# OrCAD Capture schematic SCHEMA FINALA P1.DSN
size A
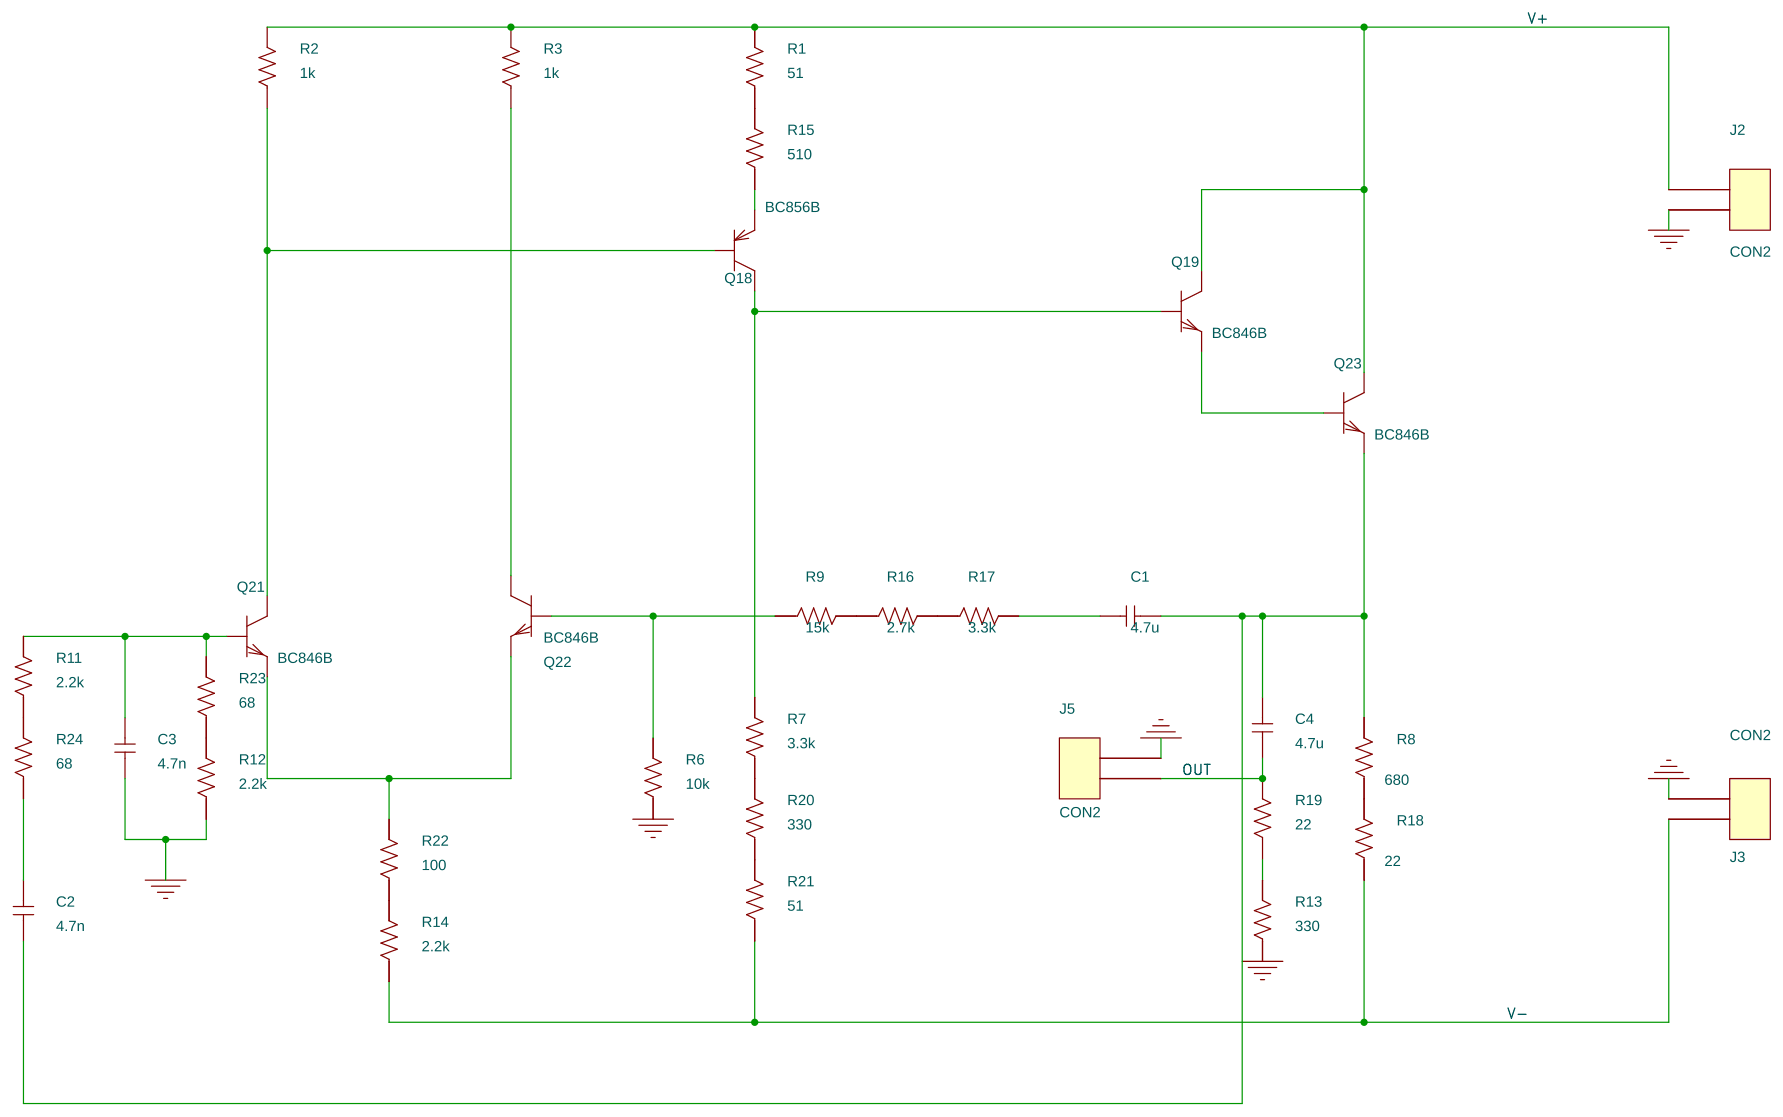
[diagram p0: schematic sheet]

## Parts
C1  4.7u  [SMC0805]
C2  4.7n  [SMC0805]
C3  4.7n  [SMC0805]
C4  4.7u  [SMC0805]
J2  CON2  [SMR2512]
J3  CON2  [SMR2512]
J5  CON2  [SMR2512]
Q18  BC856B  [TO236AA]
Q19  BC846B  [TO236AA]
Q21  BC846B  [TO236AA]
Q22  BC846B  [TO236AA]
Q23  BC846B  [TO236AA]
R1  51  [SMR0805]
R2  1k  [SMR0805]
R3  1k  [SMR0805]
R6  10k  [SMR0805]
R7  3.3k  [SMR0805]
R8  680  [SMR0805]
R9  15k  [SMR0805]
R11  2.2k  [SMR0805]
R12  2.2k  [SMR0805]
R13  330  [SMR0805]
R14  2.2k  [SMR0805]
R15  510  [SMR0805]
R16  2.7k  [SMR0805]
R17  3.3k  [SMR0805]
R18  22  [SMR0805]
R19  22  [SMR0805]
R20  330  [SMR0805]
R21  51  [SMR0805]
R22  100  [SMR0805]
R23  68  [SMR0805]
R24  68  [SMR0805]

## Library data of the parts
C1-C4 = C
J2 J3 J5 = CON2
Q18 = BC856B
Q19 Q21-Q23 = BC846B
R1-R3 R6-R9 R11-R24 = R

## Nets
GND: C3.1 J2.2 J3.2 J5.2 R6.1 R12.1 R13.1
OUT: C4.1 J5.1 R19.2
V+: J2.1 Q19.3(c) Q23.3(c) R1.2 R2.2 R3.2
V-: J3.1 R14.1 R18.1 R21.1
N26441: Q18.1(b) Q21.3(c) R2.1
N26445: Q22.3(c) R3.1
N26529: Q18.3(c) Q19.1(b) R7.2
N26571: Q19.2(e) Q23.1(b)
N26607: C1.2 C2.1 C4.2 Q23.2(e) R8.2
N26701: Q22.1(b) R6.2 R9.1
N26745: C3.2 Q21.1(b) R11.2 R23.2
N26773: Q21.2(e) Q22.2(e) R22.2
N27689: Q18.2(e) R15.1
N27789: C1.1 R17.2
N27965: R13.2 R19.1
N28453: C2.2 R24.1
N29569: R12.2 R23.1
N29570: R1.1 R15.2
N29571: R20.1 R21.2
N29572: R11.1 R24.2
N29573: R14.2 R22.1
N29574: R7.1 R20.2
N29575: R16.2 R17.1
N29576: R9.2 R16.1
N29577: R8.1 R18.2
